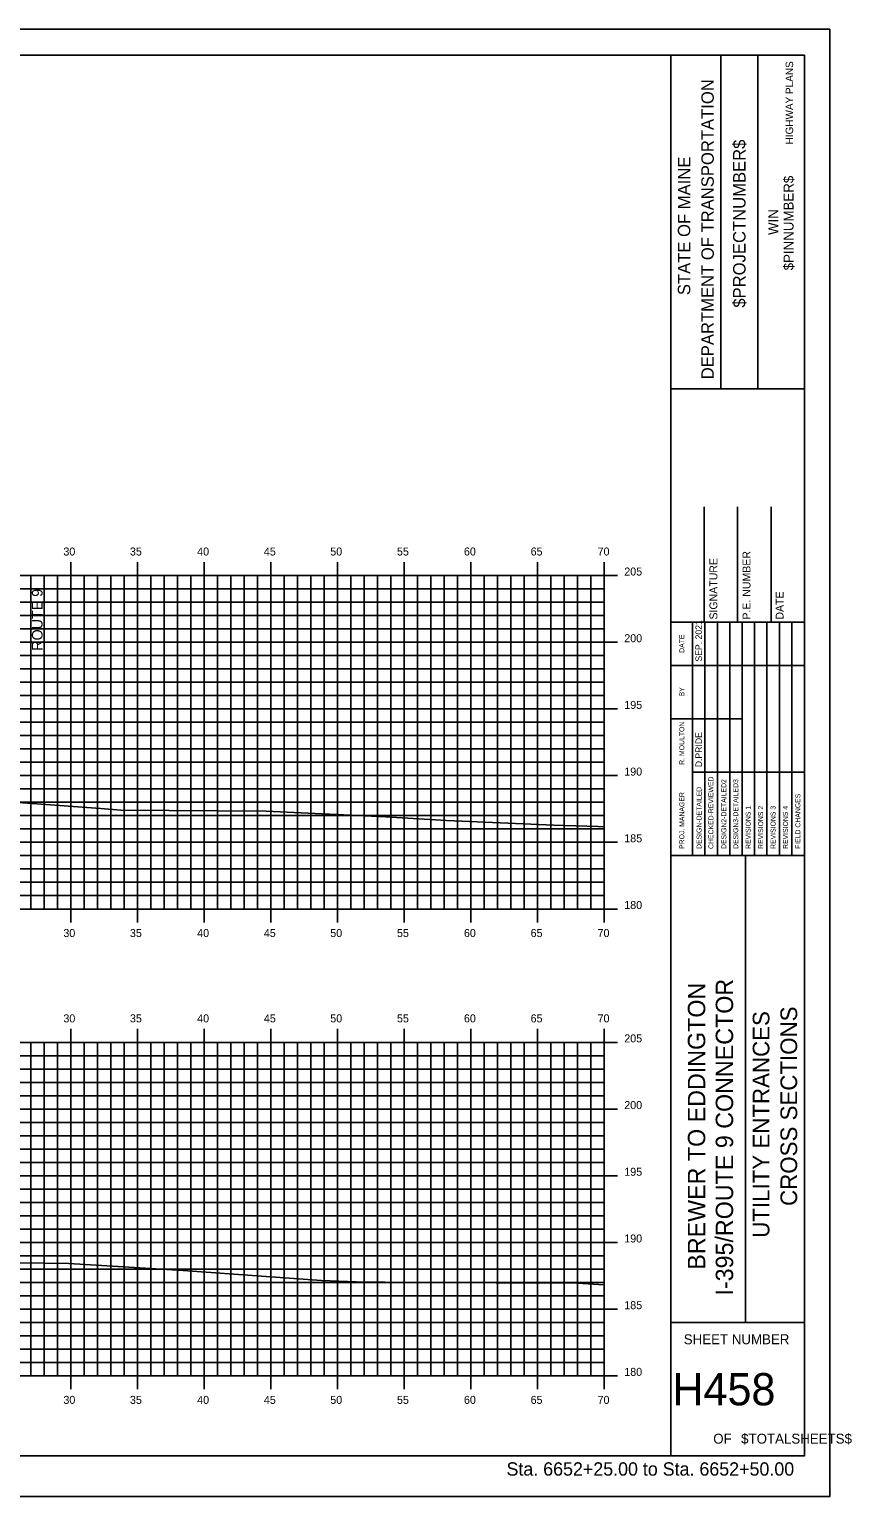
# Model space of a CAD drawing. Extents: x 1723986 to 1724158, y 458501 to 458611.
# Drawn here: x 1724096.2 to 1724157.8, y 458501.2 to 458611.2 of the extents above; entities that cross this region are included whole.
import ezdxf

# ---------------------------------------------------------------- set-up
doc = ezdxf.new("R2010")
doc.units = 0
for name, color, linetype in [('ANNOTATION', 7, 'Continuous'), ('BORDER', 7, 'Continuous'), ('H_V ANNOTATION', 7, 'Continuous'), ('HIGHWAY_TITLE', 7, 'Continuous'), ('MAJOR', 7, 'Continuous'), ('MINOR', 7, 'Continuous'), ('PLOT BOUNDARY', 7, 'Continuous'), ('S_Roadway_Centerline', 7, 'Continuous')]:
    doc.layers.add(name, color=color, linetype=linetype)

msp = doc.modelspace()

# ---------------------------------------------------------------- linework, layer by layer
at = {"layer": 'BORDER'}
for p, q in [((1724144.3, 458504.25), (1724144.3, 458609.25)), ((1724148.03, 458584.25), (1724148.03, 458609.25)), ((1724150.82, 458584.25), (1724150.82, 458609.25)), ((1724144.3, 458584.25), (1724154.3, 458584.25)), ((1724146.8, 458566.76), (1724146.8, 458575.4)), ((1724149.3, 458566.76), (1724149.3, 458575.4)), ((1724151.8, 458566.76), (1724151.8, 458575.4)), ((1724144.3, 458566.76), (1724154.3, 458566.76)), ((1724144.3, 458549.26), (1724154.3, 458549.26)), ((1724149.89, 458514.26), (1724149.89, 458549.26)), ((1724144.3, 458514.26), (1724154.3, 458514.26))]:
    msp.add_line(p, q, dxfattribs=at)
msp.add_lwpolyline([(1723994.3, 458504.25), (1724154.3, 458504.25), (1724154.3, 458609.25), (1723994.3, 458609.25)], close=True, dxfattribs=at)
for points in [[(1724145.91, 458563.51), (1724145.91, 458566.76)], [(1724145.91, 458549.26), (1724145.91, 458566.05)], [(1724146.85, 458549.26), (1724146.85, 458566.76)], [(1724147.78, 458566.76), (1724147.78, 458549.26)], [(1724148.71, 458549.26), (1724148.71, 458566.76)], [(1724149.64, 458549.26), (1724149.64, 458566.76)], [(1724150.57, 458549.26), (1724150.57, 458566.76)], [(1724151.5, 458549.26), (1724151.5, 458566.76)], [(1724152.44, 458549.26), (1724152.44, 458566.76)], [(1724153.37, 458549.26), (1724153.37, 458566.76)], [(1724144.3, 458563.51), (1724154.3, 458563.51)], [(1724144.3, 458559.51), (1724145.91, 458559.51)], [(1724145.91, 458559.51), (1724149.64, 458559.51)], [(1724145.91, 458555.51), (1724154.3, 458555.51)]]:
    msp.add_lwpolyline(points, dxfattribs=at)
at = {"layer": 'MAJOR'}
for p, q in [((1723999.3, 458570.25), (1724139.3, 458570.25)), ((1723999.3, 458570.25), (1724139.3, 458570.25)), ((1724099.3, 458571.26), (1724099.3, 458570.25)), ((1724099.3, 458545.25), (1724099.3, 458570.25)), ((1724104.3, 458571.26), (1724104.3, 458570.25)), ((1724104.3, 458545.25), (1724104.3, 458570.25)), ((1724109.3, 458571.26), (1724109.3, 458570.25)), ((1724109.3, 458545.25), (1724109.3, 458570.25)), ((1724114.3, 458571.26), (1724114.3, 458570.25)), ((1724114.3, 458545.25), (1724114.3, 458570.25)), ((1724119.3, 458571.26), (1724119.3, 458570.25)), ((1724119.3, 458545.25), (1724119.3, 458570.25)), ((1724124.3, 458571.26), (1724124.3, 458570.25)), ((1724124.3, 458545.25), (1724124.3, 458570.25)), ((1724129.3, 458571.26), (1724129.3, 458570.25)), ((1724129.3, 458545.25), (1724129.3, 458570.25)), ((1724134.3, 458571.26), (1724134.3, 458570.25)), ((1724134.3, 458545.25), (1724134.3, 458570.25)), ((1724140.3, 458570.25), (1724138.3, 458570.25)), ((1724139.3, 458571.26), (1724139.3, 458570.25)), ((1724139.3, 458545.25), (1724139.3, 458570.25)), ((1724139.3, 458545.25), (1724139.3, 458570.25)), ((1723999.3, 458565.25), (1724139.3, 458565.25)), ((1724140.3, 458565.25), (1724138.3, 458565.25)), ((1723999.3, 458560.25), (1724139.3, 458560.25)), ((1724140.3, 458560.25), (1724138.3, 458560.25)), ((1723999.3, 458555.25), (1724139.3, 458555.25)), ((1724140.3, 458555.25), (1724138.3, 458555.25)), ((1723999.3, 458550.25), (1724139.3, 458550.25)), ((1724140.3, 458550.25), (1724138.3, 458550.25)), ((1723999.3, 458545.25), (1724139.3, 458545.25)), ((1723999.3, 458545.25), (1724139.3, 458545.25)), ((1724099.3, 458544.25), (1724099.3, 458545.25)), ((1724104.3, 458544.25), (1724104.3, 458545.25)), ((1724109.3, 458544.25), (1724109.3, 458545.25)), ((1724114.3, 458544.25), (1724114.3, 458545.25)), ((1724119.3, 458544.25), (1724119.3, 458545.25)), ((1724124.3, 458544.25), (1724124.3, 458545.25)), ((1724129.3, 458544.25), (1724129.3, 458545.25)), ((1724134.3, 458544.25), (1724134.3, 458545.25)), ((1724140.3, 458545.25), (1724138.3, 458545.25)), ((1724139.3, 458544.25), (1724139.3, 458545.25)), ((1724099.3, 458536.26), (1724099.3, 458535.25)), ((1724104.3, 458536.26), (1724104.3, 458535.25)), ((1724109.3, 458536.26), (1724109.3, 458535.25)), ((1724114.3, 458536.26), (1724114.3, 458535.25)), ((1724119.3, 458536.26), (1724119.3, 458535.25)), ((1724124.3, 458536.26), (1724124.3, 458535.25)), ((1724129.3, 458536.26), (1724129.3, 458535.25)), ((1724134.3, 458536.26), (1724134.3, 458535.25)), ((1724139.3, 458536.26), (1724139.3, 458535.25)), ((1723999.3, 458535.25), (1724139.3, 458535.25)), ((1723999.3, 458535.25), (1724139.3, 458535.25)), ((1724099.3, 458510.25), (1724099.3, 458535.25)), ((1724104.3, 458510.25), (1724104.3, 458535.25)), ((1724109.3, 458510.25), (1724109.3, 458535.25)), ((1724114.3, 458510.25), (1724114.3, 458535.25)), ((1724119.3, 458510.25), (1724119.3, 458535.25)), ((1724124.3, 458510.25), (1724124.3, 458535.25)), ((1724129.3, 458510.25), (1724129.3, 458535.25)), ((1724134.3, 458510.25), (1724134.3, 458535.25)), ((1724140.3, 458535.25), (1724138.3, 458535.25)), ((1724139.3, 458510.25), (1724139.3, 458535.25)), ((1724139.3, 458510.25), (1724139.3, 458535.25)), ((1723999.3, 458530.25), (1724139.3, 458530.25)), ((1724140.3, 458530.25), (1724138.3, 458530.25)), ((1723999.3, 458525.25), (1724139.3, 458525.25)), ((1724140.3, 458525.25), (1724138.3, 458525.25)), ((1723999.3, 458520.25), (1724139.3, 458520.25)), ((1724140.3, 458520.25), (1724138.3, 458520.25)), ((1723999.3, 458515.25), (1724139.3, 458515.25)), ((1724140.3, 458515.25), (1724138.3, 458515.25)), ((1723999.3, 458510.25), (1724139.3, 458510.25)), ((1723999.3, 458510.25), (1724139.3, 458510.25)), ((1724099.3, 458509.25), (1724099.3, 458510.25)), ((1724104.3, 458509.25), (1724104.3, 458510.25)), ((1724109.3, 458509.25), (1724109.3, 458510.25)), ((1724114.3, 458509.25), (1724114.3, 458510.25)), ((1724119.3, 458509.25), (1724119.3, 458510.25)), ((1724124.3, 458509.25), (1724124.3, 458510.25)), ((1724129.3, 458509.25), (1724129.3, 458510.25)), ((1724134.3, 458509.25), (1724134.3, 458510.25)), ((1724140.3, 458510.25), (1724138.3, 458510.25)), ((1724139.3, 458509.25), (1724139.3, 458510.25))]:
    msp.add_line(p, q, dxfattribs=at)
at = {"layer": 'MINOR'}
for p, q in [((1724096.3, 458545.25), (1724096.3, 458570.25)), ((1724097.3, 458545.25), (1724097.3, 458570.25)), ((1724098.3, 458545.25), (1724098.3, 458570.25)), ((1724100.3, 458545.25), (1724100.3, 458570.25)), ((1724101.3, 458545.25), (1724101.3, 458570.25)), ((1724102.3, 458545.25), (1724102.3, 458570.25)), ((1724103.3, 458545.25), (1724103.3, 458570.25)), ((1724105.3, 458545.25), (1724105.3, 458570.25)), ((1724106.3, 458545.25), (1724106.3, 458570.25)), ((1724107.3, 458545.25), (1724107.3, 458570.25)), ((1724108.3, 458545.25), (1724108.3, 458570.25)), ((1724110.3, 458545.25), (1724110.3, 458570.25)), ((1724111.3, 458545.25), (1724111.3, 458570.25)), ((1724112.3, 458545.25), (1724112.3, 458570.25)), ((1724113.3, 458545.25), (1724113.3, 458570.25)), ((1724115.3, 458545.25), (1724115.3, 458570.25)), ((1724116.3, 458545.25), (1724116.3, 458570.25)), ((1724117.3, 458545.25), (1724117.3, 458570.25)), ((1724118.3, 458545.25), (1724118.3, 458570.25)), ((1724120.3, 458545.25), (1724120.3, 458570.25)), ((1724121.3, 458545.25), (1724121.3, 458570.25)), ((1724122.3, 458545.25), (1724122.3, 458570.25)), ((1724123.3, 458545.25), (1724123.3, 458570.25)), ((1724125.3, 458545.25), (1724125.3, 458570.25)), ((1724126.3, 458545.25), (1724126.3, 458570.25)), ((1724127.3, 458545.25), (1724127.3, 458570.25)), ((1724128.3, 458545.25), (1724128.3, 458570.25)), ((1724130.3, 458545.25), (1724130.3, 458570.25)), ((1724131.3, 458545.25), (1724131.3, 458570.25)), ((1724132.3, 458545.25), (1724132.3, 458570.25)), ((1724133.3, 458545.25), (1724133.3, 458570.25)), ((1724135.3, 458545.25), (1724135.3, 458570.25)), ((1724136.3, 458545.25), (1724136.3, 458570.25)), ((1724137.3, 458545.25), (1724137.3, 458570.25)), ((1724138.3, 458545.25), (1724138.3, 458570.25)), ((1723999.3, 458569.25), (1724139.3, 458569.25)), ((1724139.3, 458569.25), (1724138.3, 458569.25)), ((1723999.3, 458568.25), (1724139.3, 458568.25)), ((1724139.3, 458568.25), (1724138.3, 458568.25)), ((1723999.3, 458567.25), (1724139.3, 458567.25)), ((1724139.3, 458567.25), (1724138.3, 458567.25)), ((1723999.3, 458566.25), (1724139.3, 458566.25)), ((1724139.3, 458566.25), (1724138.3, 458566.25)), ((1723999.3, 458564.25), (1724139.3, 458564.25)), ((1724139.3, 458564.25), (1724138.3, 458564.25)), ((1723999.3, 458563.25), (1724139.3, 458563.25)), ((1724139.3, 458563.25), (1724138.3, 458563.25)), ((1723999.3, 458562.25), (1724139.3, 458562.25)), ((1724139.3, 458562.25), (1724138.3, 458562.25)), ((1723999.3, 458561.25), (1724139.3, 458561.25)), ((1724139.3, 458561.25), (1724138.3, 458561.25)), ((1723999.3, 458559.25), (1724139.3, 458559.25)), ((1724139.3, 458559.25), (1724138.3, 458559.25)), ((1723999.3, 458558.25), (1724139.3, 458558.25)), ((1724139.3, 458558.25), (1724138.3, 458558.25)), ((1723999.3, 458557.25), (1724139.3, 458557.25)), ((1724139.3, 458557.25), (1724138.3, 458557.25)), ((1723999.3, 458556.25), (1724139.3, 458556.25)), ((1724139.3, 458556.25), (1724138.3, 458556.25)), ((1723999.3, 458554.25), (1724139.3, 458554.25)), ((1724139.3, 458554.25), (1724138.3, 458554.25)), ((1723999.3, 458553.25), (1724139.3, 458553.25)), ((1724139.3, 458553.25), (1724138.3, 458553.25)), ((1723999.3, 458552.25), (1724139.3, 458552.25)), ((1724139.3, 458552.25), (1724138.3, 458552.25)), ((1723999.3, 458551.25), (1724139.3, 458551.25)), ((1724139.3, 458551.25), (1724138.3, 458551.25)), ((1723999.3, 458549.25), (1724139.3, 458549.25)), ((1723999.3, 458548.25), (1724139.3, 458548.25)), ((1724139.3, 458549.25), (1724138.3, 458549.25)), ((1724139.3, 458548.25), (1724138.3, 458548.25)), ((1723999.3, 458547.25), (1724139.3, 458547.25)), ((1724139.3, 458547.25), (1724138.3, 458547.25)), ((1723999.3, 458546.25), (1724139.3, 458546.25)), ((1724139.3, 458546.25), (1724138.3, 458546.25)), ((1724096.3, 458510.25), (1724096.3, 458535.25)), ((1724097.3, 458510.25), (1724097.3, 458535.25)), ((1724098.3, 458510.25), (1724098.3, 458535.25)), ((1724100.3, 458510.25), (1724100.3, 458535.25)), ((1724101.3, 458510.25), (1724101.3, 458535.25)), ((1724102.3, 458510.25), (1724102.3, 458535.25)), ((1724103.3, 458510.25), (1724103.3, 458535.25)), ((1724105.3, 458510.25), (1724105.3, 458535.25)), ((1724106.3, 458510.25), (1724106.3, 458535.25)), ((1724107.3, 458510.25), (1724107.3, 458535.25)), ((1724108.3, 458510.25), (1724108.3, 458535.25)), ((1724110.3, 458510.25), (1724110.3, 458535.25)), ((1724111.3, 458510.25), (1724111.3, 458535.25)), ((1724112.3, 458510.25), (1724112.3, 458535.25)), ((1724113.3, 458510.25), (1724113.3, 458535.25)), ((1724115.3, 458510.25), (1724115.3, 458535.25)), ((1724116.3, 458510.25), (1724116.3, 458535.25)), ((1724117.3, 458510.25), (1724117.3, 458535.25)), ((1724118.3, 458510.25), (1724118.3, 458535.25)), ((1724120.3, 458510.25), (1724120.3, 458535.25)), ((1724121.3, 458510.25), (1724121.3, 458535.25)), ((1724122.3, 458510.25), (1724122.3, 458535.25)), ((1724123.3, 458510.25), (1724123.3, 458535.25)), ((1724125.3, 458510.25), (1724125.3, 458535.25)), ((1724126.3, 458510.25), (1724126.3, 458535.25)), ((1724127.3, 458510.25), (1724127.3, 458535.25)), ((1724128.3, 458510.25), (1724128.3, 458535.25)), ((1724130.3, 458510.25), (1724130.3, 458535.25)), ((1724131.3, 458510.25), (1724131.3, 458535.25)), ((1724132.3, 458510.25), (1724132.3, 458535.25)), ((1724133.3, 458510.25), (1724133.3, 458535.25)), ((1724135.3, 458510.25), (1724135.3, 458535.25)), ((1724136.3, 458510.25), (1724136.3, 458535.25)), ((1724137.3, 458510.25), (1724137.3, 458535.25)), ((1724138.3, 458510.25), (1724138.3, 458535.25)), ((1723999.3, 458534.25), (1724139.3, 458534.25)), ((1724139.3, 458534.25), (1724138.3, 458534.25)), ((1723999.3, 458533.25), (1724139.3, 458533.25)), ((1724139.3, 458533.25), (1724138.3, 458533.25)), ((1723999.3, 458532.25), (1724139.3, 458532.25)), ((1724139.3, 458532.25), (1724138.3, 458532.25)), ((1723999.3, 458531.25), (1724139.3, 458531.25)), ((1724139.3, 458531.25), (1724138.3, 458531.25)), ((1723999.3, 458529.25), (1724139.3, 458529.25)), ((1724139.3, 458529.25), (1724138.3, 458529.25)), ((1723999.3, 458528.25), (1724139.3, 458528.25)), ((1724139.3, 458528.25), (1724138.3, 458528.25)), ((1723999.3, 458527.25), (1724139.3, 458527.25)), ((1723999.3, 458526.25), (1724139.3, 458526.25)), ((1724139.3, 458527.25), (1724138.3, 458527.25)), ((1724139.3, 458526.25), (1724138.3, 458526.25)), ((1723999.3, 458524.25), (1724139.3, 458524.25)), ((1724139.3, 458524.25), (1724138.3, 458524.25)), ((1723999.3, 458523.25), (1724139.3, 458523.25)), ((1724139.3, 458523.25), (1724138.3, 458523.25)), ((1723999.3, 458522.25), (1724139.3, 458522.25)), ((1724139.3, 458522.25), (1724138.3, 458522.25)), ((1723999.3, 458521.25), (1724139.3, 458521.25)), ((1724139.3, 458521.25), (1724138.3, 458521.25)), ((1723999.3, 458519.25), (1724139.3, 458519.25)), ((1724139.3, 458519.25), (1724138.3, 458519.25)), ((1723999.3, 458518.25), (1724139.3, 458518.25)), ((1724139.3, 458518.25), (1724138.3, 458518.25)), ((1723999.3, 458517.25), (1724139.3, 458517.25)), ((1724139.3, 458517.25), (1724138.3, 458517.25)), ((1723999.3, 458516.25), (1724139.3, 458516.25)), ((1724139.3, 458516.25), (1724138.3, 458516.25)), ((1723999.3, 458514.25), (1724139.3, 458514.25)), ((1724139.3, 458514.25), (1724138.3, 458514.25)), ((1723999.3, 458513.25), (1724139.3, 458513.25)), ((1724139.3, 458513.25), (1724138.3, 458513.25)), ((1723999.3, 458512.25), (1724139.3, 458512.25)), ((1724139.3, 458512.25), (1724138.3, 458512.25)), ((1723999.3, 458511.25), (1724139.3, 458511.25)), ((1724139.3, 458511.25), (1724138.3, 458511.25))]:
    msp.add_line(p, q, dxfattribs=at)
at = {"layer": 'PLOT BOUNDARY'}
msp.add_lwpolyline([(1723986.21, 458501.2), (1724156.21, 458501.2), (1724156.21, 458611.2), (1723986.21, 458611.2)], close=True, dxfattribs=at)
at = {"layer": 'S_Roadway_Centerline'}
for points in [[(1723999.3, 458555.22), (1724004.93, 458555.02), (1724008.8, 458554.9), (1724018.87, 458554.84), (1724037, 458554.45), (1724042.32, 458554.38), (1724060.47, 458554.09), (1724065.64, 458554), (1724068.91, 458553.87), (1724078.57, 458553.42), (1724084.41, 458553.6), (1724090.91, 458553.55), (1724101.53, 458552.78), (1724103.05, 458552.67), (1724113.96, 458552.58), (1724122.9, 458552.15), (1724127.48, 458551.88), (1724135.52, 458551.54), (1724138.83, 458551.43), (1724139.3, 458551.41)], [(1723999.3, 458520.4), (1724001.14, 458520.3), (1724004.1, 458520.32), (1724014.81, 458520.28), (1724021.99, 458520.23), (1724026.56, 458520.11), (1724036.11, 458519.54), (1724041.36, 458519.56), (1724060.09, 458519.21), (1724072.33, 458518.85), (1724079.59, 458518.68), (1724093.49, 458518.76), (1724099.17, 458518.67), (1724107.74, 458518.16), (1724118.11, 458517.41), (1724120.7, 458517.29), (1724125.08, 458517.24), (1724137.3, 458517.19), (1724139.3, 458517.07)]]:
    msp.add_lwpolyline(points, dxfattribs=at)

# ---------------------------------------------------------------- texts
at = {"layer": 'ANNOTATION'}
msp.add_text('ROUTE 9', height=0.8, rotation=90, dxfattribs=at).set_placement((1724097.19, 458564.61))
at = {"layer": 'BORDER'}
for s, height, p in [('DEPARTMENT OF TRANSPORTATION', 0.9318, (1724147.51, 458584.96)), ('$PROJECTNUMBER$', 0.9318, (1724149.89, 458590.33)), ('STATE OF MAINE', 0.9318, (1724145.75, 458591.27)), ('$PINNUMBER$', 0.7453, (1724153.49, 458593.13)), ('WIN', 0.745, (1724152.34, 458595.78)), ('SIGNATURE', 0.591, (1724147.78, 458566.95)), ('P.E. NUMBER', 0.5906, (1724150.26, 458566.95)), ('DATE', 0.591, (1724152.74, 458566.95)), ('SEP. 2021', 0.485, (1724146.62, 458563.8)), ('DATE', 0.371, (1724145.3, 458564.46)), ('BY', 0.371, (1724145.3, 458561.19)), ('R. MOULTON', 0.373, (1724145.3, 458556.06)), ('D.PRIDE', 0.485, (1724146.62, 458555.88)), ('CHECKED-REVIEWED', 0.3727, (1724147.48, 458549.75)), ('PROJ. MANAGER', 0.3727, (1724145.3, 458549.75)), ('DESIGN-DETAILED', 0.3727, (1724146.59, 458549.75)), ('DESIGN2-DETAILED2', 0.3727, (1724148.45, 458549.75)), ('DESIGN3-DETAILED3', 0.3727, (1724149.34, 458549.75)), ('FIELD CHANGES', 0.3727, (1724154, 458549.75)), ('REVISIONS 1', 0.3727, (1724150.27, 458549.75)), ('REVISIONS 2', 0.3727, (1724151.21, 458549.75)), ('REVISIONS 3', 0.3727, (1724152.14, 458549.75)), ('REVISIONS 4', 0.3727, (1724153.07, 458549.75)), ('UTILITY ENTRANCES', 1.25, (1724151.68, 458520.6)), ('CROSS SECTIONS', 1.25, (1724153.76, 458522.99))]:
    msp.add_text(s, height=height, rotation=90, dxfattribs=at).set_placement(p)
for s, height, p in [('SHEET NUMBER', 0.7453, (1724145.26, 458512.62)), ('H458', 2.419, (1724144.4, 458508.04)), ('OF', 0.745, (1724147.47, 458505.17)), ('$TOTALSHEETS$', 0.7453, (1724149.56, 458505.17))]:
    msp.add_text(s, height=height, dxfattribs=at).set_placement(p)
at = {"layer": 'H_V ANNOTATION'}
for s, height, p in [('30', 0.6, (1724098.75, 458571.75)), ('35', 0.6, (1724103.74, 458571.75)), ('40', 0.6, (1724108.78, 458571.75)), ('45', 0.6, (1724113.78, 458571.75)), ('50', 0.6, (1724118.76, 458571.75)), ('55', 0.6, (1724123.76, 458571.75)), ('60', 0.6, (1724128.78, 458571.75)), ('65', 0.6, (1724133.78, 458571.75)), ('70', 0.6, (1724138.8, 458571.75)), ('205', 0.6, (1724140.8, 458570.25)), ('200', 0.6, (1724140.8, 458565.25)), ('195', 0.6, (1724140.8, 458560.25)), ('190', 0.6, (1724140.8, 458555.25)), ('185', 0.6, (1724140.8, 458550.25)), ('180', 0.6, (1724140.8, 458545.25)), ('30', 0.6, (1724098.75, 458543.15)), ('35', 0.6, (1724103.74, 458543.15)), ('40', 0.6, (1724108.78, 458543.15)), ('45', 0.6, (1724113.78, 458543.15)), ('50', 0.6, (1724118.76, 458543.15)), ('55', 0.6, (1724123.76, 458543.15)), ('60', 0.6, (1724128.78, 458543.15)), ('65', 0.6, (1724133.78, 458543.15)), ('70', 0.6, (1724138.8, 458543.15)), ('30', 0.6, (1724098.75, 458536.75)), ('35', 0.6, (1724103.74, 458536.75)), ('40', 0.6, (1724108.78, 458536.75)), ('45', 0.6, (1724113.78, 458536.75)), ('50', 0.6, (1724118.76, 458536.75)), ('55', 0.6, (1724123.76, 458536.75)), ('60', 0.6, (1724128.78, 458536.75)), ('65', 0.6, (1724133.78, 458536.75)), ('70', 0.6, (1724138.8, 458536.75)), ('205', 0.6, (1724140.8, 458535.25)), ('200', 0.6, (1724140.8, 458530.25)), ('195', 0.6, (1724140.8, 458525.25)), ('190', 0.6, (1724140.8, 458520.25)), ('185', 0.6, (1724140.8, 458515.25)), ('180', 0.6, (1724140.8, 458510.25)), ('30', 0.6, (1724098.75, 458508.15)), ('35', 0.6, (1724103.74, 458508.15)), ('40', 0.6, (1724108.78, 458508.15)), ('45', 0.6, (1724113.78, 458508.15)), ('50', 0.6, (1724118.76, 458508.15)), ('55', 0.6, (1724123.76, 458508.15)), ('60', 0.6, (1724128.78, 458508.15)), ('65', 0.6, (1724133.78, 458508.15)), ('70', 0.6, (1724138.8, 458508.15)), ('Sta. 6652+25.00 to Sta. 6652+50.00', 1.0002, (1724131.97, 458502.77))]:
    msp.add_text(s, height=height, dxfattribs=at).set_placement(p)
at = {"layer": 'HIGHWAY_TITLE'}
for s, height, p in [('HIGHWAY PLANS', 0.559, (1724153.46, 458602.57)), ('BREWER TO EDDINGTON', 1.3043, (1724146.87, 458518.21)), ('I-395/ROUTE 9 CONNECTOR', 1.3043, (1724148.96, 458516.27))]:
    msp.add_text(s, height=height, rotation=90, dxfattribs=at).set_placement(p)

doc.saveas('drawing.dxf')
